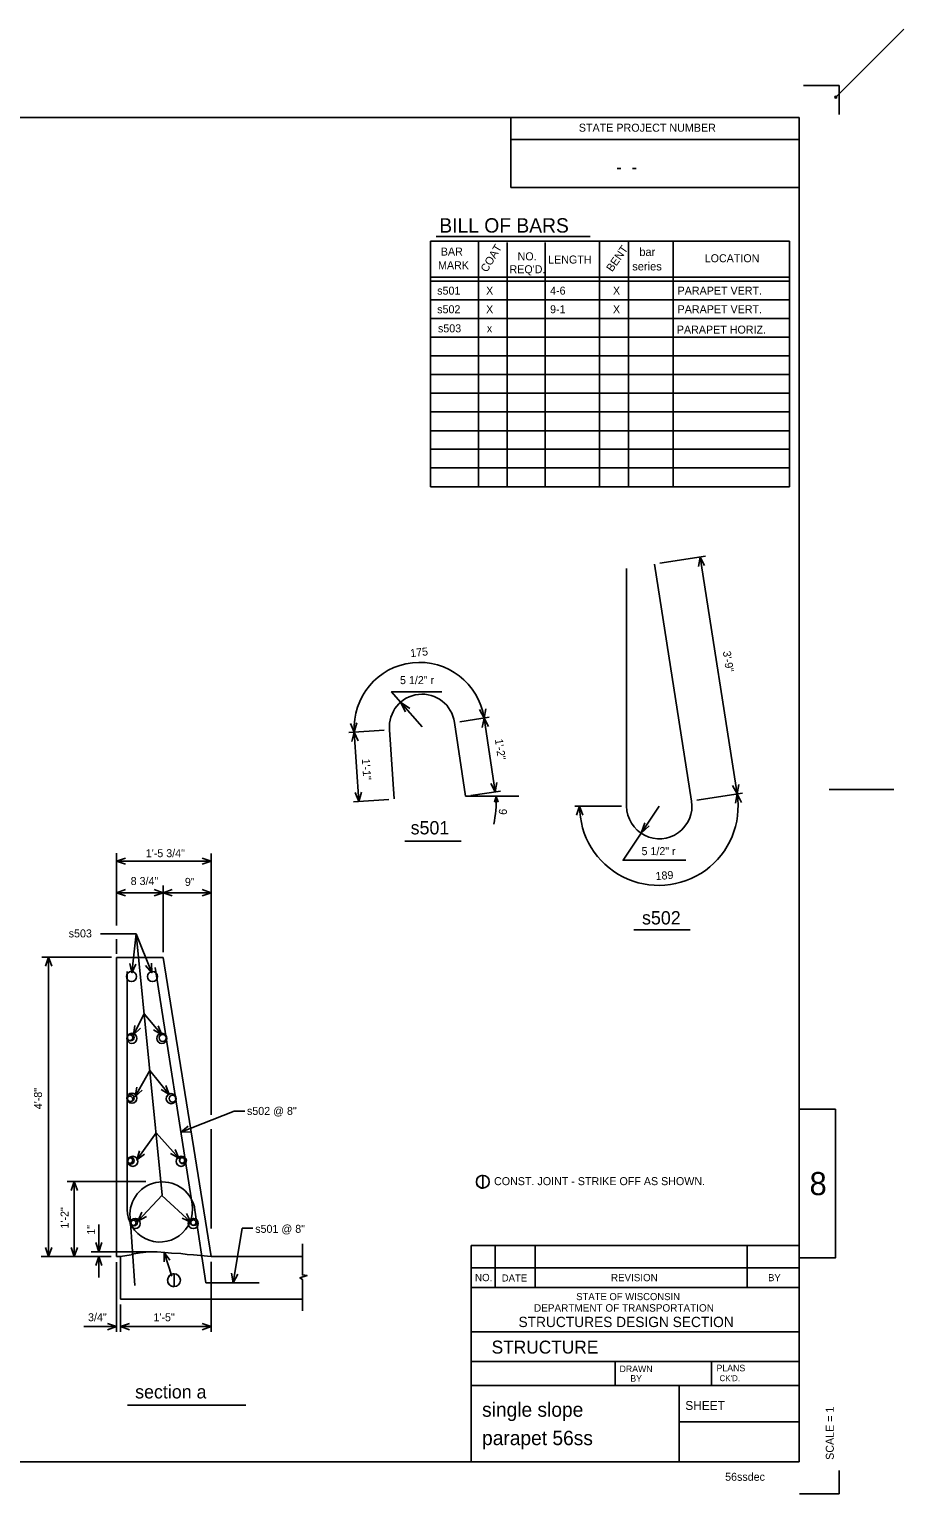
# Model space of a CAD drawing. Extents: x -38.4 to -2.2, y 84.9 to 109.4.
# Drawn here: x -15.84 to -2.17, y 85.97 to 108.85 of the extents above; entities that cross this region are included whole.
import ezdxf

# ---------------------------------------------------------------- set-up
doc = ezdxf.new("R2010")
doc.units = 0
for name, color, linetype in [('Default', 7, 'Continuous'), ('Level 1', 7, 'Continuous'), ('Level 2', 7, 'Continuous'), ('Level 37', 7, 'Continuous'), ('Level 49', 7, 'Continuous')]:
    doc.layers.add(name, color=color, linetype=linetype)

msp = doc.modelspace()

# ---------------------------------------------------------------- linework, layer by layer
at = {"layer": 'Default'}
for p, q in [((-14.473, 94.846), (-14.473, 95.978)), ((-14.473, 95.851), (-12.994, 95.851)), ((-12.994, 94.526), (-12.994, 95.97)), ((-13.744, 94.428), (-13.744, 95.471)), ((-14.473, 95.358), (-13.744, 95.358)), ((-13.744, 95.358), (-12.994, 95.358)), ((-14.168, 94.719), (-14.722, 94.719)), ((-14.232, 94.11), (-14.168, 94.719)), ((-14.168, 94.719), (-13.759, 90.637)), ((-14.168, 94.719), (-13.919, 94.11)), ((-12.994, 91.891), (-12.994, 94.809)), ((-14.473, 94.428), (-14.473, 94.634)), ((-14.473, 94.407), (-14.473, 94.617)), ((-14.55, 94.355), (-15.639, 94.355)), ((-15.533, 89.678), (-15.533, 94.355)), ((-14.473, 94.345), (-13.744, 94.345)), ((-14.473, 94.345), (-14.473, 89.678)), ((-12.994, 89.678), (-13.744, 94.345)), ((-14.304, 94.126), (-14.304, 90.412)), ((-13.291, 90.492), (-13.869, 94.193)), ((-14.206, 93.138), (-14.043, 93.469)), ((-14.043, 93.469), (-13.767, 93.138)), ((-14.181, 92.175), (-13.954, 92.581)), ((-13.954, 92.581), (-13.649, 92.209)), ((-12.633, 91.949), (-13.467, 91.617)), ((-12.466, 91.949), (-12.633, 91.949)), ((-14.156, 91.186), (-13.856, 91.609)), ((-13.856, 91.609), (-13.497, 91.212)), ((-12.994, 90.113), (-12.994, 91.664)), ((-14.017, 90.847), (-15.245, 90.847)), ((-15.133, 89.678), (-15.133, 90.847)), ((-8.748, 90.743), (-8.748, 90.943)), ((-8.748, 90.743), (-8.748, 90.943)), ((-13.759, 90.637), (-14.139, 90.231)), ((-13.311, 90.214), (-13.763, 90.632)), ((-13.078, 89.267), (-13.248, 90.4)), ((-14.75, 89.752), (-14.75, 90.178)), ((-14.189, 89.226), (-14.262, 90.286)), ((-12.509, 90.121), (-12.652, 89.267)), ((-12.342, 90.121), (-12.509, 90.121)), ((-14.557, 89.678), (-15.649, 89.678)), ((-15.213, 89.678), (-15.05, 89.678)), ((-13.943, 89.752), (-14.871, 89.752)), ((-14.75, 89.349), (-14.75, 89.678)), ((-14.473, 89.678), (-14.411, 89.678)), ((-14.411, 89.678), (-14.411, 89.011)), ((-13.611, 89.371), (-13.727, 89.741)), ((-11.568, 89.678), (-12.994, 89.678)), ((-14.473, 89.586), (-14.473, 88.498)), ((-12.994, 89.595), (-12.994, 88.498)), ((-13.573, 89.204), (-13.573, 89.405)), ((-13.078, 89.267), (-12.244, 89.267)), ((-14.411, 89.011), (-11.568, 89.011)), ((-14.411, 88.928), (-14.411, 88.498)), ((-14.473, 88.581), (-14.982, 88.581)), ((-14.411, 88.581), (-12.994, 88.581)), ((-14.302, 87.356), (-12.451, 87.356))]:
    msp.add_line(p, q, dxfattribs=at)
for points in [[(-14.333, 95.803), (-14.473, 95.851), (-14.333, 95.9)], [(-13.135, 95.9), (-12.994, 95.851), (-13.135, 95.803)], [(-14.333, 95.309), (-14.473, 95.358), (-14.333, 95.407)], [(-13.885, 95.407), (-13.744, 95.358), (-13.885, 95.309)], [(-13.603, 95.309), (-13.744, 95.358), (-13.603, 95.407)], [(-13.135, 95.407), (-12.994, 95.358), (-13.135, 95.309)], [(-15.582, 94.214), (-15.533, 94.355), (-15.484, 94.214)], [(-14.169, 94.245), (-14.232, 94.11), (-14.265, 94.256)], [(-13.927, 94.259), (-13.919, 94.11), (-14.018, 94.222)], [(-14.1, 93.243), (-14.206, 93.138), (-14.187, 93.286)], [(-13.82, 93.278), (-13.767, 93.138), (-13.895, 93.216)], [(-14.07, 92.274), (-14.181, 92.175), (-14.155, 92.322)], [(-13.7, 92.349), (-13.649, 92.209), (-13.776, 92.287)], [(-13.318, 91.624), (-13.467, 91.617), (-13.354, 91.714)], [(-14.035, 91.273), (-14.156, 91.186), (-14.114, 91.329)], [(-13.555, 91.349), (-13.497, 91.212), (-13.627, 91.284)], [(-15.182, 90.706), (-15.133, 90.847), (-15.084, 90.706)], [(-14.007, 90.301), (-14.139, 90.231), (-14.078, 90.367)], [(-13.381, 90.346), (-13.311, 90.214), (-13.447, 90.274)], [(-13.355, 90.297), (-13.311, 90.214), (-13.396, 90.252)], [(-15.484, 89.819), (-15.533, 89.678), (-15.582, 89.819)], [(-15.084, 89.819), (-15.133, 89.678), (-15.182, 89.819)], [(-14.701, 89.893), (-14.75, 89.752), (-14.798, 89.893)], [(-14.798, 89.537), (-14.75, 89.678), (-14.701, 89.537)], [(-14.411, 89.678), (-14.245, 89.7), (-14.233, 89.712), (-14.101, 89.734), (-13.966, 89.752), (-13.837, 89.749), (-13.717, 89.737), (-13.616, 89.728), (-13.469, 89.725), (-13.371, 89.71), (-13.269, 89.7), (-12.994, 89.678)], [(-13.731, 89.592), (-13.727, 89.741), (-13.638, 89.621)], [(-11.568, 88.826), (-11.568, 89.319), (-11.609, 89.341), (-11.497, 89.382), (-11.568, 89.388), (-11.568, 89.874)], [(-12.58, 89.398), (-12.652, 89.267), (-12.676, 89.414)], [(-14.614, 88.63), (-14.473, 88.581), (-14.614, 88.533)], [(-14.27, 88.533), (-14.411, 88.581), (-14.27, 88.63)], [(-13.135, 88.63), (-12.994, 88.581), (-13.135, 88.533)]]:
    msp.add_lwpolyline(points, dxfattribs=at)
for points in [[(-8.748, 90.744), (-8.748, 90.943), (-8.748, 90.944), (-8.767, 90.943), (-8.789, 90.937), (-8.807, 90.927), (-8.826, 90.91), (-8.837, 90.895), (-8.846, 90.874), (-8.851, 90.849), (-8.849, 90.825), (-8.844, 90.807), (-8.831, 90.783), (-8.818, 90.77), (-8.802, 90.757), (-8.785, 90.75), (-8.77, 90.746), (-8.762, 90.744)], [(-8.748, 90.744), (-8.748, 90.943), (-8.748, 90.944), (-8.767, 90.943), (-8.789, 90.937), (-8.807, 90.927), (-8.826, 90.91), (-8.837, 90.895), (-8.846, 90.874), (-8.851, 90.849), (-8.849, 90.825), (-8.844, 90.807), (-8.831, 90.783), (-8.818, 90.77), (-8.802, 90.757), (-8.785, 90.75), (-8.77, 90.746), (-8.762, 90.744)], [(-13.573, 89.205), (-13.573, 89.405), (-13.573, 89.405), (-13.592, 89.404), (-13.614, 89.399), (-13.632, 89.388), (-13.651, 89.372), (-13.662, 89.356), (-13.671, 89.335), (-13.676, 89.31), (-13.673, 89.286), (-13.669, 89.269), (-13.656, 89.245), (-13.643, 89.232), (-13.627, 89.219), (-13.61, 89.212), (-13.595, 89.207), (-13.586, 89.206)]]:
    msp.add_lwpolyline(points, close=True, dxfattribs=at)
for centre, radius in [((-14.239, 94.049), 0.0788), ((-13.91, 94.049), 0.0788), ((-14.232, 93.084), 0.0788), ((-14.253, 93.099), 0.0539), ((-14.262, 93.095), 0.0417), ((-13.764, 93.084), 0.0788), ((-13.752, 93.091), 0.0539), ((-14.232, 92.15), 0.0788), ((-14.253, 92.151), 0.0539), ((-13.618, 92.142), 0.0788), ((-13.598, 92.143), 0.0539), ((-14.262, 92.137), 0.0417), ((-14.253, 91.172), 0.0539), ((-14.262, 91.175), 0.0417), ((-14.217, 91.163), 0.0788), ((-13.464, 91.163), 0.0788), ((-13.436, 91.18), 0.0539), ((-13.447, 91.178), 0.0417), ((-8.75, 90.844), 0.1), ((-8.75, 90.844), 0.1), ((-14.18, 90.192), 0.0788), ((-14.199, 90.209), 0.0539), ((-14.208, 90.203), 0.0417), ((-13.274, 90.192), 0.0788), ((-13.266, 90.217), 0.0539), ((-13.272, 90.206), 0.0417), ((-13.575, 89.306), 0.1)]:
    msp.add_circle(centre, radius, dxfattribs=at)
for centre, start, end in [((-13.753, 90.332), 7.615, 185.2003), ((-13.795, 90.412), 180, 9)]:
    msp.add_arc(centre, 0.51, start, end, dxfattribs=at)
at = {"layer": 'Level 1'}
for p, q in [((-3.184, 107.971), (-3.739, 107.971)), ((-3.184, 107.516), (-3.184, 107.971)), ((-3.809, 107.471), (-35.185, 107.471)), ((-8.315, 107.471), (-8.315, 106.375)), ((-3.809, 86.471), (-3.809, 107.471)), ((-8.315, 107.126), (-3.809, 107.126)), ((-8.315, 106.375), (-3.809, 106.375)), ((-5.489, 96.791), (-6.068, 100.492)), ((-5.985, 100.505), (-5.274, 100.616)), ((-5.356, 100.603), (-4.778, 96.902)), ((-6.503, 100.425), (-6.503, 96.711)), ((-9.699, 97.951), (-10.034, 98.336)), ((-9.02, 96.865), (-9.193, 98.019)), ((-9.111, 98.031), (-8.649, 98.1)), ((-8.731, 98.088), (-8.558, 96.934)), ((-10.29, 97.899), (-10.842, 97.861)), ((-10.685, 96.786), (-10.758, 97.867)), ((-10.133, 96.824), (-10.207, 97.905)), ((-10.217, 96.818), (-10.768, 96.781)), ((-9.02, 96.865), (-8.187, 96.865)), ((-8.938, 96.877), (-8.476, 96.946)), ((-5.407, 96.804), (-4.695, 96.915)), ((-6.586, 96.711), (-7.313, 96.711)), ((-5.993, 96.711), (-6.277, 96.287)), ((-9.97, 96.166), (-9.091, 96.166)), ((-6.392, 94.779), (-5.513, 94.779)), ((-8.934, 89.846), (-3.806, 89.846)), ((-8.934, 89.19), (-8.934, 89.846)), ((-8.555, 89.19), (-8.555, 89.846)), ((-7.93, 89.19), (-7.93, 89.846)), ((-4.618, 89.19), (-4.618, 89.846)), ((-8.934, 89.502), (-3.806, 89.502)), ((-8.934, 86.471), (-8.934, 89.19)), ((-8.934, 89.19), (-3.806, 89.19)), ((-8.934, 88.502), (-3.806, 88.502)), ((-8.934, 88.034), (-3.806, 88.034)), ((-6.683, 87.659), (-6.683, 88.034)), ((-5.176, 87.659), (-5.176, 88.034)), ((-8.934, 87.659), (-3.806, 87.659)), ((-5.684, 86.471), (-5.684, 87.659)), ((-5.683, 87.096), (-3.809, 87.096)), ((-35.185, 86.471), (-3.809, 86.471)), ((-3.184, 85.971), (-3.184, 86.334)), ((-3.802, 85.971), (-3.184, 85.971))]:
    msp.add_line(p, q, dxfattribs=at)
for points in [[(-5.382, 100.456), (-5.356, 100.603), (-5.286, 100.471)], [(-10.034, 98.336), (-10.175, 98.499), (-9.388, 98.499)], [(-9.956, 98.183), (-10.034, 98.336), (-9.893, 98.238)], [(-8.704, 98.234), (-8.731, 98.088), (-8.8, 98.22)], [(-10.719, 98.011), (-10.758, 97.867), (-10.817, 98.004)], [(-8.758, 97.941), (-8.731, 98.088), (-8.662, 97.956)], [(-10.797, 97.723), (-10.758, 97.867), (-10.7, 97.73)], [(-8.531, 97.081), (-8.558, 96.934), (-8.627, 97.066)], [(-4.751, 97.049), (-4.778, 96.902), (-4.847, 97.034)], [(-10.646, 96.93), (-10.685, 96.786), (-10.743, 96.924)], [(-4.804, 96.756), (-4.778, 96.902), (-4.708, 96.771)], [(-7.286, 96.57), (-7.238, 96.711), (-7.189, 96.57)], [(-6.15, 96.402), (-6.277, 96.287), (-6.219, 96.449)], [(-6.277, 96.287), (-6.558, 95.866), (-5.579, 95.866)]]:
    msp.add_lwpolyline(points, dxfattribs=at)
msp.add_lwpolyline([(-3.809, 91.976), (-3.242, 91.976), (-3.242, 89.654), (-3.809, 89.654)], close=True, dxfattribs=at)
for centre, radius, start, end in [((-9.74, 97.937), 1.02, 8.5231, 183.9058), ((-9.699, 97.951), 0.51, 7.615, 185.2003), ((-6, 96.711), 1.238, 180, 8.8807), ((-5.993, 96.711), 0.51, 180, 9)]:
    msp.add_arc(centre, radius, start, end, dxfattribs=at)
at = {"layer": 'Level 2'}
for p, q in [((-3.235, 107.786), (-2.175, 108.847)), ((-9.568, 105.536), (-8.343, 105.536)), ((-9.568, 105.536), (-9.568, 101.702)), ((-9.48, 105.608), (-7.072, 105.608)), ((-8.818, 105.536), (-8.818, 101.702)), ((-8.368, 105.519), (-8.368, 101.702)), ((-8.343, 105.536), (-7.775, 105.536)), ((-7.775, 105.536), (-5.775, 105.536)), ((-7.775, 105.519), (-7.775, 101.702)), ((-6.925, 105.536), (-6.925, 101.702)), ((-6.475, 105.536), (-6.475, 101.702)), ((-5.775, 105.536), (-3.958, 105.536)), ((-5.775, 105.536), (-5.775, 101.702)), ((-3.958, 105.536), (-3.958, 101.702)), ((-9.568, 104.973), (-7.775, 104.973)), ((-9.568, 104.911), (-7.775, 104.911)), ((-7.775, 104.973), (-5.775, 104.973)), ((-7.775, 104.911), (-5.775, 104.911)), ((-5.775, 104.973), (-3.958, 104.973)), ((-5.775, 104.911), (-3.958, 104.911)), ((-9.568, 104.619), (-7.775, 104.619)), ((-7.775, 104.619), (-5.775, 104.619)), ((-5.775, 104.619), (-3.958, 104.619)), ((-9.568, 104.327), (-7.775, 104.327)), ((-7.775, 104.327), (-5.775, 104.327)), ((-5.775, 104.327), (-3.958, 104.327)), ((-9.568, 104.036), (-7.775, 104.036)), ((-7.775, 104.036), (-5.775, 104.036)), ((-5.775, 104.036), (-3.958, 104.036)), ((-9.568, 103.744), (-7.775, 103.744)), ((-7.775, 103.744), (-5.775, 103.744)), ((-5.775, 103.744), (-3.958, 103.744)), ((-9.568, 103.452), (-7.775, 103.452)), ((-7.775, 103.452), (-5.775, 103.452)), ((-5.775, 103.452), (-3.958, 103.452)), ((-9.568, 103.161), (-7.775, 103.161)), ((-7.775, 103.161), (-5.775, 103.161)), ((-5.775, 103.161), (-3.958, 103.161)), ((-9.568, 102.869), (-7.775, 102.869)), ((-7.775, 102.869), (-5.775, 102.869)), ((-5.775, 102.869), (-3.958, 102.869)), ((-9.568, 102.577), (-7.775, 102.577)), ((-7.775, 102.577), (-5.775, 102.577)), ((-5.775, 102.577), (-3.958, 102.577)), ((-9.568, 102.286), (-7.775, 102.286)), ((-7.775, 102.286), (-5.775, 102.286)), ((-5.775, 102.286), (-3.958, 102.286)), ((-9.568, 101.994), (-7.775, 101.994)), ((-7.775, 101.994), (-5.775, 101.994)), ((-5.775, 101.994), (-3.958, 101.994)), ((-9.568, 101.702), (-7.775, 101.702)), ((-9.568, 101.702), (-7.775, 101.702)), ((-7.775, 101.702), (-3.958, 101.702)), ((-7.775, 101.702), (-3.958, 101.702))]:
    msp.add_line(p, q, dxfattribs=at)
msp.add_lwpolyline([(-8.57, 96.774), (-8.543, 96.863), (-8.509, 96.776)], dxfattribs=at)
msp.add_arc((-10.254, 96.793), 1.713, 347.6879, 2.3357, dxfattribs=at)
at = {"layer": 'Level 37'}
msp.add_line((-3.339, 96.971), (-2.329, 96.971), dxfattribs=at)
at = {"layer": 'Level 49'}
msp.add_circle((-3.236, 107.786), 0.0152, dxfattribs=at)

# ---------------------------------------------------------------- texts
at = {"layer": 'Default'}
for s, height, p in [('1\'-5 3/4"', 0.125, (-14.016, 95.914)), ('8 3/4"', 0.125, (-14.252, 95.479)), ('9"', 0.125, (-13.405, 95.466)), ('s503', 0.125, (-15.22, 94.661)), ('s502 @ 8"', 0.125, (-12.435, 91.888)), ('CONST. JOINT - STRIKE OFF AS SHOWN.', 0.125, (-8.575, 90.791)), ('CONST. JOINT - STRIKE OFF AS SHOWN.', 0.125, (-8.575, 90.791)), ('s501 @ 8"', 0.125, (-12.306, 90.046)), ('3/4"', 0.125, (-14.918, 88.665)), ('1\'-5"', 0.125, (-13.896, 88.665)), ('section a', 0.2083, (-14.182, 87.459)), ('56ssdec', 0.125, (-4.965, 86.173))]:
    msp.add_text(s, height=height, dxfattribs=at).set_placement(p)
for s, p in [('4\'-8"', (-15.637, 91.977)), ('1\'-2"', (-15.222, 90.113)), ('1"', (-14.807, 90.016))]:
    msp.add_text(s, height=0.125, rotation=90, dxfattribs=at).set_placement(p)
at = {"layer": 'Level 1'}
for s, height, p in [('STATE PROJECT NUMBER', 0.12525, (-7.25, 107.247)), ('    -  -  ', 0.2023, (-6.969, 106.594)), ('5 1/2" r', 0.125, (-10.044, 98.618)), ('s501', 0.2083, (-9.878, 96.27)), ('5 1/2" r', 0.125, (-6.271, 95.946)), ('s502', 0.2083, (-6.263, 94.863)), ('8', 0.361, (-3.646, 90.635)), ('NO.', 0.1139, (-8.872, 89.291)), ('DATE', 0.1109, (-8.454, 89.286)), ('REVISION', 0.1142, (-6.748, 89.29)), ('BY', 0.1108, (-4.294, 89.29)), ('STATE OF WISCONSIN', 0.11076, (-7.291, 88.995)), ('DEPARTMENT OF TRANSPORTATION', 0.11643, (-7.951, 88.815)), ('STRUCTURES DESIGN SECTION', 0.1605, (-8.193, 88.574)), ('STRUCTURE', 0.2022, (-8.613, 88.16)), ('DRAWN', 0.1022, (-6.614, 87.871)), ('PLANS', 0.1023, (-5.099, 87.883)), ('BY', 0.102, (-6.446, 87.721)), ("CK'D.", 0.0927, (-5.052, 87.729)), (' single slope ', 0.22392, (-8.845, 87.173)), ('SHEET', 0.1387, (-5.587, 87.28)), (' parapet 56ss ', 0.22392, (-8.845, 86.73))]:
    msp.add_text(s, height=height, dxfattribs=at).set_placement(p)
for s, rotation, p in [('175', 6.2145, (-9.879, 99.038)), ('3\'-9"', 278.8807, (-5.002, 99.126)), ('1\'-2"', 278.5231, (-8.563, 97.754)), ('1\'-1"', 273.9058, (-10.64, 97.449)), ('189', 4.4403, (-6.047, 95.556)), ('SCALE = 1        ', 90, (-3.267, 86.5))]:
    msp.add_text(s, height=0.125, rotation=rotation, dxfattribs=at).set_placement(p)
at = {"layer": 'Level 2'}
for s, height, p in [('BILL OF BARS', 0.225, (-9.43, 105.671)), ('BAR', 0.125, (-9.407, 105.312)), ('NO.', 0.125, (-8.207, 105.238)), ('LENGTH', 0.125, (-7.73, 105.188)), ('bar', 0.1294, (-6.305, 105.305)), ('LOCATION', 0.125, (-5.284, 105.208)), ('MARK', 0.125, (-9.45, 105.098)), ("REQ'D.", 0.125, (-8.334, 105.036)), ('series', 0.1294, (-6.416, 105.08)), ('s501', 0.125, (-9.463, 104.702)), ('X', 0.125, (-8.699, 104.702)), (' 4-6 ', 0.125, (-7.746, 104.702)), ('X', 0.125, (-6.717, 104.702)), ('PARAPET VERT.   ', 0.125, (-5.707, 104.702)), ('s502', 0.125, (-9.463, 104.411)), ('X', 0.125, (-8.699, 104.411)), (' 9-1 ', 0.125, (-7.746, 104.411)), ('X', 0.125, (-6.717, 104.411)), ('PARAPET VERT.   ', 0.125, (-5.707, 104.411)), ('s503', 0.125, (-9.451, 104.113)), ('x', 0.125, (-8.687, 104.113)), ('PARAPET HORIZ.  ', 0.125, (-5.719, 104.093))]:
    msp.add_text(s, height=height, dxfattribs=at).set_placement(p)
for s, rotation, p in [('COAT', 59.0083, (-8.687, 105.041)), ('BENT', 54.9994, (-6.73, 105.049)), ('9', 265.9161, (-8.496, 96.675))]:
    msp.add_text(s, height=0.125, rotation=rotation, dxfattribs=at).set_placement(p)

doc.saveas('drawing.dxf')
